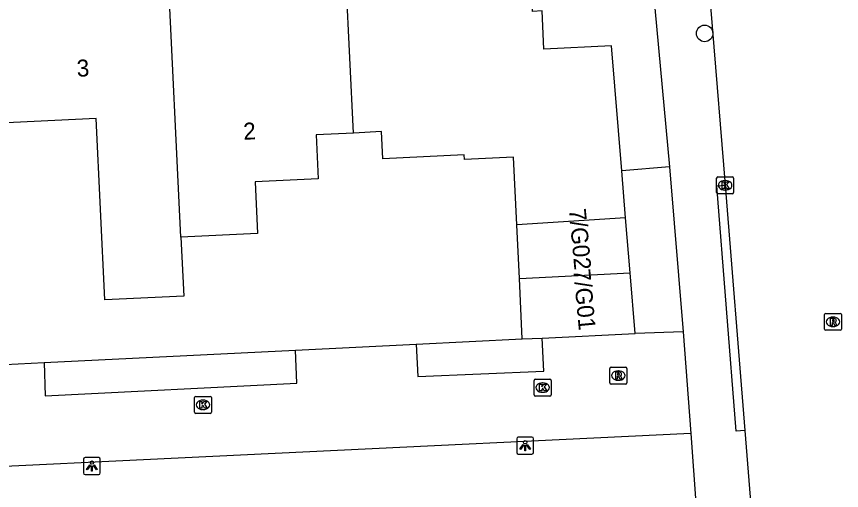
# Model space of a CAD drawing. Extents: x 161253 to 161848, y 384872 to 385383.
# Drawn here: x 161598.77 to 161647.56, y 385312.53 to 385340.54 of the extents above; entities that cross this region are included whole.
import ezdxf

# ---------------------------------------------------------------- set-up
doc = ezdxf.new("R2010")
doc.units = 0
for name, color, linetype in [('IMGEO_Boom', 7, 'Continuous'), ('IMGEO_Erf', 7, 'Continuous'), ('IMGEO_Kolk', 7, 'Continuous'), ('IMGEO_Lichtpunt', 7, 'Continuous'), ('IMGEO_Pand', 7, 'Continuous'), ('IMGEO_Pand_nummerreeks', 7, 'Continuous'), ('IMGEO_Parkeervlak_open', 7, 'Continuous'), ('IMGEO_Rijbaan_lokaal_open', 7, 'Continuous'), ('IMGEO_Rioolput', 7, 'Continuous'), ('IMGEO_Voetpad_open', 7, 'Continuous')]:
    doc.layers.add(name, color=color, linetype=linetype)

msp = doc.modelspace()

# ---------------------------------------------------------------- linework, layer by layer
at = {"layer": 'IMGEO_Boom'}
msp.add_circle((161639.463, 385339.546), 0.489, dxfattribs=at)
at = {"layer": 'IMGEO_Erf'}
msp.add_lwpolyline([(161637.387, 385331.666), (161634.556, 385331.43)], dxfattribs=at)
at = {"layer": 'IMGEO_Kolk'}
for p, q in [((161640.172, 385330.143), (161640.172, 385330.995)), ((161640.247, 385331.069), (161641.099, 385331.069)), ((161640.66, 385330.849), (161640.685, 385330.849)), ((161641.173, 385330.995), (161641.173, 385330.143)), ((161640.683, 385330.289), (161640.658, 385330.289)), ((161641.099, 385330.069), (161640.247, 385330.069)), ((161629.385, 385318.187), (161629.385, 385319.039)), ((161629.46, 385319.113), (161630.312, 385319.113)), ((161630.386, 385319.039), (161630.386, 385318.187)), ((161629.873, 385318.893), (161629.898, 385318.893)), ((161609.292, 385317.166), (161609.292, 385318.018)), ((161609.367, 385318.092), (161610.219, 385318.092)), ((161610.293, 385318.018), (161610.293, 385317.166)), ((161630.312, 385318.113), (161629.46, 385318.113)), ((161629.896, 385318.333), (161629.871, 385318.333)), ((161609.78, 385317.872), (161609.805, 385317.872)), ((161610.219, 385317.092), (161609.367, 385317.092)), ((161609.803, 385317.312), (161609.778, 385317.312))]:
    msp.add_line(p, q, dxfattribs=at)
for points in [[(161640.172, 385330.143), (161640.172, 385330.995)], [(161640.247, 385331.069), (161641.099, 385331.069)], [(161640.493, 385330.769), (161640.616, 385330.769), (161640.616, 385330.618), (161640.746, 385330.769), (161640.91, 385330.769), (161640.764, 385330.618), (161640.917, 385330.369), (161640.765, 385330.369), (161640.68, 385330.533), (161640.616, 385330.466), (161640.616, 385330.369), (161640.493, 385330.369), (161640.493, 385330.769)], [(161641.173, 385330.995), (161641.173, 385330.143)], [(161641.099, 385330.069), (161640.247, 385330.069)], [(161629.385, 385318.187), (161629.385, 385319.039)], [(161629.46, 385319.113), (161630.312, 385319.113)], [(161630.386, 385319.039), (161630.386, 385318.187)], [(161629.706, 385318.813), (161629.829, 385318.813), (161629.829, 385318.662), (161629.959, 385318.813), (161630.123, 385318.813), (161629.977, 385318.662), (161630.13, 385318.413), (161629.978, 385318.413), (161629.893, 385318.577), (161629.829, 385318.51), (161629.829, 385318.413), (161629.706, 385318.413), (161629.706, 385318.813)], [(161609.292, 385317.166), (161609.292, 385318.018)], [(161609.367, 385318.092), (161610.219, 385318.092)], [(161610.293, 385318.018), (161610.293, 385317.166)], [(161630.312, 385318.113), (161629.46, 385318.113)], [(161609.613, 385317.792), (161609.736, 385317.792), (161609.736, 385317.641), (161609.866, 385317.792), (161610.03, 385317.792), (161609.884, 385317.641), (161610.037, 385317.392), (161609.885, 385317.392), (161609.8, 385317.556), (161609.736, 385317.489), (161609.736, 385317.392), (161609.613, 385317.392), (161609.613, 385317.792)], [(161610.219, 385317.092), (161609.367, 385317.092)]]:
    msp.add_lwpolyline(points, dxfattribs=at)
for centre, start, end in [((161640.249, 385330.993), 91.552, 178.448), ((161640.249, 385330.993), 91.552, 178.448), ((161641.097, 385330.993), 1.552, 88.448), ((161641.097, 385330.993), 1.552, 88.448), ((161640.249, 385330.145), 181.552, 268.448), ((161640.249, 385330.145), 181.552, 268.448), ((161641.097, 385330.145), 271.552, 358.448), ((161641.097, 385330.145), 271.552, 358.448), ((161629.462, 385319.037), 91.552, 178.448), ((161629.462, 385319.037), 91.552, 178.448), ((161630.31, 385319.037), 1.552, 88.448), ((161630.31, 385319.037), 1.552, 88.448), ((161609.369, 385318.016), 91.552, 178.448), ((161609.369, 385318.016), 91.552, 178.448), ((161610.217, 385318.016), 1.552, 88.448), ((161610.217, 385318.016), 1.552, 88.448), ((161629.462, 385318.189), 181.552, 268.448), ((161629.462, 385318.189), 181.552, 268.448), ((161630.31, 385318.189), 271.552, 358.448), ((161630.31, 385318.189), 271.552, 358.448), ((161609.369, 385317.168), 181.552, 268.448), ((161609.369, 385317.168), 181.552, 268.448), ((161610.217, 385317.168), 271.552, 358.448), ((161610.217, 385317.168), 271.552, 358.448)]:
    msp.add_arc(centre, 0.0765, start, end, dxfattribs=at)
for centre, major_axis, ratio, start_param, end_param in [((161640.659, 385330.569), (-0.387, 0.002), 0.722429, 4.712389, 7.853982), ((161640.684, 385330.569), (-0.39, 0.002), 0.717154, 1.570796, 4.712389), ((161629.872, 385318.613), (-0.387, 0.002), 0.722429, 4.712389, 7.853982), ((161629.897, 385318.613), (-0.39, 0.002), 0.717154, 1.570796, 4.712389), ((161609.779, 385317.592), (-0.387, 0.002), 0.722429, 4.712389, 7.853982), ((161609.804, 385317.592), (-0.39, 0.002), 0.717154, 1.570796, 4.712389)]:
    msp.add_ellipse(centre, major_axis=major_axis, ratio=ratio, start_param=start_param, end_param=end_param, dxfattribs=at)
at = {"layer": 'IMGEO_Lichtpunt'}
for p, q in [((161628.35, 385315.588), (161628.35, 385314.781)), ((161628.35, 385315.588), (161628.35, 385314.781)), ((161629.252, 385315.683), (161628.444, 385315.683)), ((161629.252, 385315.683), (161628.444, 385315.683)), ((161629.346, 385314.781), (161629.346, 385315.588)), ((161629.346, 385314.781), (161629.346, 385315.588)), ((161628.444, 385314.687), (161629.252, 385314.687)), ((161628.444, 385314.687), (161629.252, 385314.687)), ((161602.728, 385314.38), (161602.728, 385313.573)), ((161602.728, 385314.38), (161602.728, 385313.573)), ((161603.63, 385314.475), (161602.822, 385314.475)), ((161603.63, 385314.475), (161602.822, 385314.475)), ((161603.724, 385313.573), (161603.724, 385314.38)), ((161603.724, 385313.573), (161603.724, 385314.38)), ((161602.822, 385313.479), (161603.63, 385313.479)), ((161602.822, 385313.479), (161603.63, 385313.479))]:
    msp.add_line(p, q, dxfattribs=at)
for points in [[(161628.724, 385315.252), (161628.763, 385315.224), (161628.575, 385314.962), (161628.537, 385314.989), (161628.724, 385315.252)], [(161628.826, 385315.204), (161628.873, 385315.204), (161628.873, 385314.882), (161628.826, 385314.882), (161628.826, 385315.204)], [(161628.936, 385315.224), (161628.974, 385315.251), (161629.161, 385314.989), (161629.122, 385314.961), (161628.936, 385315.224)], [(161603.102, 385314.044), (161603.141, 385314.016), (161602.953, 385313.754), (161602.915, 385313.781), (161603.102, 385314.044)], [(161603.204, 385313.996), (161603.251, 385313.996), (161603.251, 385313.674), (161603.204, 385313.674), (161603.204, 385313.996)], [(161603.314, 385314.016), (161603.352, 385314.043), (161603.539, 385313.781), (161603.5, 385313.753), (161603.314, 385314.016)]]:
    msp.add_lwpolyline(points, dxfattribs=at)
for centre in [(161628.849, 385315.386), (161603.227, 385314.178)]:
    msp.add_circle(centre, 0.0994, dxfattribs=at)
for centre, start, end in [((161628.444, 385315.588), 90, 180), ((161628.444, 385315.588), 90, 180), ((161629.252, 385315.588), 0, 90), ((161629.252, 385315.588), 0, 90), ((161628.444, 385314.781), 180, 270), ((161628.444, 385314.781), 180, 270), ((161629.252, 385314.781), 270, 0), ((161629.252, 385314.781), 270, 360), ((161602.822, 385314.38), 90, 180), ((161602.822, 385314.38), 90, 180), ((161603.63, 385314.38), 0, 90), ((161603.63, 385314.38), 0, 90), ((161602.822, 385313.573), 180, 270), ((161602.822, 385313.573), 180, 270), ((161603.63, 385313.573), 270, 0), ((161603.63, 385313.573), 270, 360)]:
    msp.add_arc(centre, 0.0946, start, end, dxfattribs=at)
at = {"layer": 'IMGEO_Pand'}
for points in [[(161634.556, 385331.43), (161633.951, 385338.802), (161629.959, 385338.607), (161629.849, 385340.876), (161629.291, 385340.849), (161629.109, 385344.564), (161620.333, 385344.136), (161620.404, 385342.68), (161618.26, 385342.575)], [(161608.495, 385327.511), (161607.714, 385343.512)], [(161618.696, 385333.659), (161618.26, 385342.575)], [(161608.495, 385327.511), (161608.663, 385324.024), (161604, 385323.799), (161603.484, 385334.512), (161597.356, 385334.216), (161597.312, 385334.824), (161597.265, 385335.499)], [(161618.696, 385333.659), (161616.491, 385333.551), (161616.617, 385330.948), (161612.881, 385330.767), (161613.028, 385327.728), (161608.495, 385327.511)], [(161628.351, 385328.237), (161628.157, 385332.229), (161625.258, 385332.088), (161625.244, 385332.376), (161620.424, 385332.141), (161620.347, 385333.739), (161618.696, 385333.659)], [(161634.784, 385328.645), (161634.556, 385331.43)], [(161634.784, 385328.645), (161628.351, 385328.237)], [(161628.506, 385325.068), (161628.351, 385328.237)], [(161635.051, 385325.386), (161634.784, 385328.645)], [(161628.506, 385325.068), (161635.051, 385325.386)], [(161635.344, 385321.813), (161635.051, 385325.386)], [(161628.68, 385321.487), (161628.506, 385325.068)], [(161628.68, 385321.487), (161629.848, 385321.544)], [(161629.848, 385321.544), (161635.344, 385321.813)]]:
    msp.add_lwpolyline(points, dxfattribs=at)
at = {"layer": 'IMGEO_Parkeervlak_open'}
for points in [[(161622.411, 385321.177), (161628.68, 385321.487)], [(161600.41, 385320.091), (161615.263, 385320.824)]]:
    msp.add_lwpolyline(points, dxfattribs=at)
at = {"layer": 'IMGEO_Rijbaan_lokaal_open'}
for points in [[(161638.047, 385352.37), (161638.34, 385351.916), (161638.591, 385351.437), (161638.799, 385350.937), (161638.962, 385350.421), (161639.077, 385349.893), (161639.145, 385349.356), (161640.674, 385330.569)], [(161640.674, 385330.569), (161641.833, 385316.072)], [(161638.202, 385321.9), (161635.344, 385321.813)], [(161638.202, 385321.9), (161638.643, 385315.896)], [(161622.411, 385321.177), (161622.497, 385319.266), (161629.956, 385319.579), (161629.848, 385321.544)], [(161615.263, 385320.824), (161622.411, 385321.177)], [(161600.41, 385320.091), (161600.471, 385318.132), (161615.349, 385318.875), (161615.263, 385320.824)], [(161596.55, 385319.9), (161600.41, 385320.091)], [(161641.833, 385316.072), (161642.309, 385310.17)], [(161638.643, 385315.896), (161589.461, 385313.536), (161587.705, 385313.449)]]:
    msp.add_lwpolyline(points, dxfattribs=at)
at = {"layer": 'IMGEO_Rioolput'}
for p, q in [((161646.554, 385322.074), (161646.554, 385322.926)), ((161646.629, 385323), (161647.481, 385323)), ((161647.555, 385322.926), (161647.555, 385322.074)), ((161647.042, 385322.78), (161647.067, 385322.78)), ((161647.481, 385322), (161646.629, 385322)), ((161647.065, 385322.22), (161647.04, 385322.22)), ((161633.855, 385318.897), (161633.855, 385319.749)), ((161633.93, 385319.823), (161634.782, 385319.823)), ((161634.343, 385319.603), (161634.368, 385319.603)), ((161634.856, 385319.749), (161634.856, 385318.897)), ((161634.366, 385319.043), (161634.341, 385319.043)), ((161634.782, 385318.823), (161633.93, 385318.823))]:
    msp.add_line(p, q, dxfattribs=at)
for points in [[(161646.554, 385322.074), (161646.554, 385322.926)], [(161646.629, 385323), (161647.481, 385323)], [(161647.555, 385322.926), (161647.555, 385322.074)], [(161647.143, 385322.698), (161646.891, 385322.7), (161646.891, 385322.3)], [(161646.891, 385322.3), (161647.015, 385322.3), (161647.015, 385322.462), (161647.026, 385322.462)], [(161647.069, 385322.619), (161647.015, 385322.619), (161647.015, 385322.538)], [(161647.015, 385322.538), (161647.067, 385322.538)], [(161647.073, 385322.433), (161647.144, 385322.3), (161647.284, 385322.3), (161647.219, 385322.426)], [(161647.481, 385322), (161646.629, 385322)], [(161633.855, 385318.897), (161633.855, 385319.749)], [(161633.93, 385319.823), (161634.782, 385319.823)], [(161634.444, 385319.521), (161634.192, 385319.523), (161634.192, 385319.123)], [(161634.37, 385319.442), (161634.316, 385319.442), (161634.316, 385319.361)], [(161634.856, 385319.749), (161634.856, 385318.897)], [(161634.192, 385319.123), (161634.316, 385319.123), (161634.316, 385319.285), (161634.327, 385319.285)], [(161634.316, 385319.361), (161634.368, 385319.361)], [(161634.374, 385319.256), (161634.445, 385319.123), (161634.585, 385319.123), (161634.52, 385319.249)], [(161634.782, 385318.823), (161633.93, 385318.823)]]:
    msp.add_lwpolyline(points, dxfattribs=at)
for centre, radius, start, end in [((161646.631, 385322.924), 0.0765, 91.552, 178.448), ((161646.631, 385322.924), 0.0765, 91.552, 178.448), ((161647.479, 385322.924), 0.0765, 1.552, 88.448), ((161647.479, 385322.924), 0.0765, 1.552, 88.448), ((161647.025, 385322.409), 0.0533, 26.0293, 88.6989), ((161647.051, 385322.727), 0.19, 274.7715, 282.9687), ((161647.075, 385322.523), 0.0964, 77.0061, 93.1865), ((161647.089, 385322.58), 0.0378, 276.6634, 79.6772), ((161647.142, 385322.588), 0.109, 350.3612, 89.416), ((161647.14, 385322.588), 0.112, 277.5842, 350.9817), ((161647.124, 385322.373), 0.108, 29.5134, 73.7905), ((161646.631, 385322.076), 0.0765, 181.552, 268.448), ((161646.631, 385322.076), 0.0765, 181.552, 268.448), ((161647.479, 385322.076), 0.0765, 271.552, 358.448), ((161647.479, 385322.076), 0.0765, 271.552, 358.448), ((161633.932, 385319.747), 0.0765, 91.552, 178.448), ((161633.932, 385319.747), 0.0765, 91.552, 178.448), ((161634.376, 385319.346), 0.0964, 77.0061, 93.1865), ((161634.39, 385319.403), 0.0378, 276.6634, 79.6772), ((161634.443, 385319.411), 0.109, 350.3612, 89.416), ((161634.78, 385319.747), 0.0765, 1.552, 88.448), ((161634.78, 385319.747), 0.0765, 1.552, 88.448), ((161634.326, 385319.232), 0.0533, 26.0293, 88.6989), ((161634.352, 385319.55), 0.19, 274.7715, 282.9687), ((161634.441, 385319.411), 0.112, 277.5842, 350.9817), ((161634.425, 385319.196), 0.108, 29.5134, 73.7905), ((161633.932, 385318.899), 0.0765, 181.552, 268.448), ((161633.932, 385318.899), 0.0765, 181.552, 268.448), ((161634.78, 385318.899), 0.0765, 271.552, 358.448), ((161634.78, 385318.899), 0.0765, 271.552, 358.448)]:
    msp.add_arc(centre, radius, start, end, dxfattribs=at)
for centre, major_axis, ratio, start_param, end_param in [((161647.041, 385322.5), (-0.387, 0.002), 0.722429, 4.712389, 7.853982), ((161647.066, 385322.5), (-0.39, 0.002), 0.717154, 1.570796, 4.712389), ((161634.342, 385319.323), (-0.387, 0.002), 0.722429, 4.712389, 7.853982), ((161634.367, 385319.323), (-0.39, 0.002), 0.717154, 1.570796, 4.712389)]:
    msp.add_ellipse(centre, major_axis=major_axis, ratio=ratio, start_param=start_param, end_param=end_param, dxfattribs=at)
at = {"layer": 'IMGEO_Voetpad_open'}
for points in [[(161635.651, 385350.437), (161637.387, 385331.666)], [(161637.387, 385331.666), (161638.202, 385321.9)], [(161641.833, 385316.072), (161641.335, 385316.033), (161640.176, 385330.53), (161640.674, 385330.569)], [(161638.643, 385315.896), (161638.964, 385311.532), (161639.748, 385301.503), (161640.058, 385301.531), (161641.615, 385301.67)]]:
    msp.add_lwpolyline(points, dxfattribs=at)

# ---------------------------------------------------------------- texts
at = {"layer": 'IMGEO_Pand_nummerreeks'}
for s, rotation, p in [('3', 2.7674, (161602.353, 385336.98)), ('2', 2.7737, (161612.199, 385333.256)), ('7/G02', 275.2578, (161631.432, 385329.157)), ('7/G01', 275.3145, (161631.693, 385325.586))]:
    msp.add_text(s, height=1, rotation=rotation, dxfattribs=at).set_placement(p)

doc.saveas('drawing.dxf')
